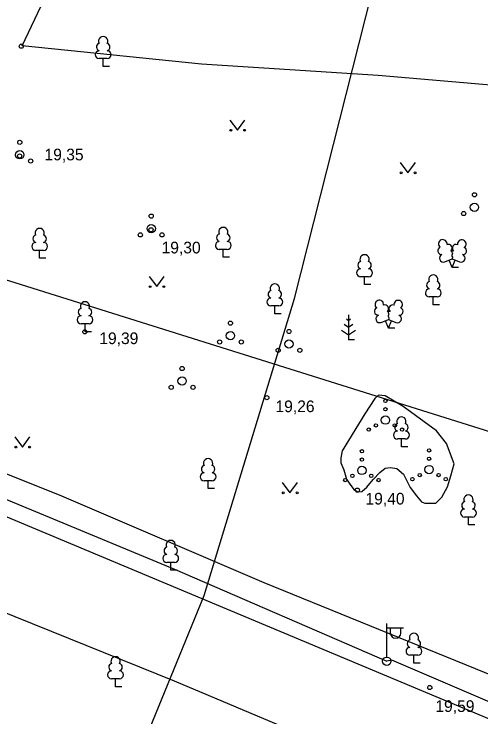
# Model space of a CAD drawing. Extents: x 713497 to 713863, y 6590062 to 6590327.
# Drawn here: x 713754.44 to 713782.43, y 6590236.16 to 6590278.31 of the extents above; entities that cross this region are included whole.
import ezdxf

# ---------------------------------------------------------------- set-up
doc = ezdxf.new("R2010")
doc.units = 0
for name, color, linetype in [('AED', 7, 'Continuous'), ('HALJASTUS', 7, 'Continuous'), ('KORGUS', 7, 'Continuous'), ('KPKAABEL', 7, 'Continuous'), ('MPKAABEL', 7, 'Continuous'), ('POST', 7, 'Continuous'), ('PUU', 7, 'Continuous'), ('SITRASS', 7, 'Continuous'), ('TEE', 7, 'Continuous'), ('TTRASS', 7, 'Continuous')]:
    doc.layers.add(name, color=color, linetype=linetype)

msp = doc.modelspace()

# ---------------------------------------------------------------- linework, layer by layer
at = {"layer": 'AED'}
msp.add_lwpolyline([(713788.88, 6590285.23), (713788.26, 6590278.65), (713788.03, 6590278.65), (713787.17, 6590278.25), (713785.85, 6590277.29), (713784.83, 6590276.5), (713784.01, 6590275.55), (713783.55, 6590274.76), (713783.25, 6590274.03), (713776.26, 6590274.62), (713765.67, 6590275.3), (713754.93, 6590276.41), (713757.56, 6590281.99), (713749.75, 6590289.16), (713748.93, 6590295.3), (713750.19, 6590299.43)], dxfattribs=at)
at = {"layer": 'HALJASTUS'}
for p, q in [((713767.367, 6590271.947), (713767.83, 6590271.34)), ((713767.83, 6590271.34), (713768.276, 6590271.947)), ((713777.587, 6590269.397), (713778.05, 6590268.79)), ((713778.05, 6590268.79), (713778.496, 6590269.397)), ((713762.527, 6590262.567), (713762.99, 6590261.96)), ((713762.99, 6590261.96), (713763.436, 6590262.567)), ((713754.477, 6590252.947), (713754.94, 6590252.34)), ((713754.94, 6590252.34), (713755.386, 6590252.947)), ((713770.517, 6590250.207), (713770.98, 6590249.6)), ((713770.98, 6590249.6), (713771.426, 6590250.207))]:
    msp.add_line(p, q, dxfattribs=at)
msp.add_lwpolyline([(713774.21, 6590250.97), (713774.36, 6590250.42), (713774.53, 6590250.17), (713774.8, 6590249.79), (713775.05, 6590249.66), (713775.28, 6590249.67), (713775.58, 6590249.94), (713775.96, 6590250.39), (713776.36, 6590250.81), (713776.69, 6590251.07), (713777.01, 6590251.11), (713777.39, 6590251.06), (713777.79, 6590250.71), (713778.19, 6590249.91), (713778.57, 6590249.41), (713778.87, 6590249.06), (713779.07, 6590248.97), (713779.44, 6590248.97), (713779.72, 6590248.97), (713780.09, 6590249.34), (713780.42, 6590249.96), (713780.62, 6590250.62), (713780.82, 6590251.34), (713780.37, 6590252.55), (713779.77, 6590253.32), (713777.77, 6590254.77), (713776.68, 6590255.42), (713776.29, 6590255.45), (713776.06, 6590255.25), (713775.46, 6590254.33), (713774.11, 6590252.12), (713774.03, 6590251.69), (713774.03, 6590251.39), (713774.21, 6590250.97)], dxfattribs=at)
for centre, radius in [((713767.429, 6590271.34), 0.055), ((713768.258, 6590271.34), 0.055), ((713754.78, 6590270.62), 0.125), ((713754.78, 6590269.87), 0.25), ((713755.43, 6590269.495), 0.125), ((713777.649, 6590268.79), 0.055), ((713778.478, 6590268.79), 0.055), ((713782.04, 6590267.47), 0.125), ((713782.04, 6590266.72), 0.25), ((713762.66, 6590266.19), 0.125), ((713781.39, 6590266.345), 0.125), ((713762.66, 6590265.44), 0.25), ((713762.01, 6590265.065), 0.125), ((713763.31, 6590265.065), 0.125), ((713762.589, 6590261.96), 0.055), ((713763.418, 6590261.96), 0.055), ((713767.41, 6590259.77), 0.125), ((713770.92, 6590259.27), 0.125), ((713767.41, 6590259.02), 0.25), ((713766.76, 6590258.645), 0.125), ((713768.06, 6590258.645), 0.125), ((713770.92, 6590258.52), 0.25), ((713770.27, 6590258.145), 0.125), ((713771.57, 6590258.145), 0.125), ((713764.51, 6590257.05), 0.125), ((713764.51, 6590256.3), 0.25), ((713763.86, 6590255.925), 0.125), ((713765.16, 6590255.925), 0.125), ((713776.7, 6590255.11), 0.1), ((713776.7, 6590254.61), 0.1), ((713776.7, 6590253.96), 0.25), ((713775.7, 6590253.385), 0.1), ((713776.135, 6590253.635), 0.1), ((713777.265, 6590253.635), 0.1), ((713777.7, 6590253.385), 0.1), ((713754.539, 6590252.34), 0.055), ((713755.368, 6590252.34), 0.055), ((713779.32, 6590252.14), 0.1), ((713775.29, 6590252.09), 0.1), ((713775.29, 6590251.59), 0.1), ((713779.32, 6590251.64), 0.1), ((713775.29, 6590250.94), 0.25), ((713779.32, 6590250.99), 0.25), ((713774.725, 6590250.615), 0.1), ((713775.855, 6590250.615), 0.1), ((713778.32, 6590250.415), 0.1), ((713778.755, 6590250.665), 0.1), ((713779.885, 6590250.665), 0.1), ((713780.32, 6590250.415), 0.1), ((713774.29, 6590250.365), 0.1), ((713776.29, 6590250.365), 0.1), ((713770.579, 6590249.6), 0.055), ((713771.408, 6590249.6), 0.055)]:
    msp.add_circle(centre, radius, dxfattribs=at)
at = {"layer": 'KORGUS'}
for centre in [(713754.87, 6590276.38), (713754.77, 6590269.8), (713762.65, 6590265.37), (713758.68, 6590259.25), (713769.59, 6590255.3), (713775.02, 6590249.76), (713779.36, 6590237.92)]:
    msp.add_circle(centre, 0.125, dxfattribs=at)
at = {"layer": 'KPKAABEL'}
msp.add_lwpolyline([(713815.88, 6590242.79), (713794.35, 6590249.68), (713754.19, 6590262.29), (713731.48, 6590269.02), (713706.45, 6590275.72)], dxfattribs=at)
at = {"layer": 'MPKAABEL'}
for points in [[(713701.219, 6590274.33), (713701.679, 6590274.524), (713703.015, 6590271.361), (713705.012, 6590272.169), (713706.295, 6590269.173), (713709.564, 6590267.835), (713721.885, 6590262.655), (713734.411, 6590257.594), (713748.424, 6590251.492), (713764.059, 6590245.013), (713776.78, 6590239.5)], [(713802.35, 6590228.73), (713777.08, 6590239.56), (713776.78, 6590239.5)]]:
    msp.add_lwpolyline(points, dxfattribs=at)
at = {"layer": 'POST'}
for p, q in [((713776.78, 6590239.75), (713776.78, 6590241.75)), ((713776.78, 6590241.5), (713777.78, 6590241.5)), ((713777.007, 6590241.179), (713777.007, 6590241.5)), ((713777.619, 6590241.179), (713777.619, 6590241.5))]:
    msp.add_line(p, q, dxfattribs=at)
msp.add_circle((713776.78, 6590239.5), 0.25, dxfattribs=at)
msp.add_arc((713777.313, 6590241.179), 0.306, 180, 0, dxfattribs=at)
at = {"layer": 'PUU'}
for p, q in [((713760.02, 6590275.635), (713759.54, 6590275.635)), ((713759.78, 6590275.16), (713759.78, 6590275.635)), ((713760.16, 6590275.16), (713759.78, 6590275.16)), ((713756.21, 6590264.135), (713755.73, 6590264.135)), ((713755.97, 6590263.66), (713755.97, 6590264.135)), ((713767.22, 6590264.195), (713766.74, 6590264.195)), ((713766.98, 6590263.72), (713766.98, 6590264.195)), ((713756.35, 6590263.66), (713755.97, 6590263.66)), ((713767.36, 6590263.72), (713766.98, 6590263.72)), ((713780.26, 6590263.445), (713780.705, 6590263.62)), ((713780.705, 6590263.62), (713781.145, 6590263.44)), ((713780.7, 6590263.11), (713780.525, 6590263.55)), ((713780.7, 6590263.11), (713780.88, 6590263.55)), ((713781.08, 6590263.11), (713780.7, 6590263.11)), ((713775.69, 6590262.555), (713775.21, 6590262.555)), ((713775.45, 6590262.08), (713775.45, 6590262.555)), ((713775.83, 6590262.08), (713775.45, 6590262.08)), ((713779.81, 6590261.345), (713779.33, 6590261.345)), ((713779.57, 6590260.87), (713779.57, 6590261.345)), ((713770.31, 6590260.805), (713769.83, 6590260.805)), ((713770.07, 6590260.33), (713770.07, 6590260.805)), ((713779.95, 6590260.87), (713779.57, 6590260.87)), ((713770.45, 6590260.33), (713770.07, 6590260.33)), ((713774.49, 6590260.27), (713774.49, 6590258.77)), ((713774.49, 6590259.92), (713774.366, 6590260.003)), ((713774.614, 6590260.003), (713774.49, 6590259.92)), ((713776.45, 6590259.815), (713776.895, 6590259.99)), ((713776.89, 6590259.48), (713776.715, 6590259.92)), ((713776.89, 6590259.48), (713777.07, 6590259.92)), ((713776.895, 6590259.99), (713777.335, 6590259.81)), ((713758.93, 6590259.735), (713758.45, 6590259.735)), ((713758.69, 6590259.26), (713758.69, 6590259.735)), ((713774.066, 6590259.359), (713774.49, 6590259.077)), ((713774.49, 6590259.52), (713774.223, 6590259.698)), ((713774.757, 6590259.698), (713774.49, 6590259.52)), ((713774.49, 6590259.077), (713774.914, 6590259.359)), ((713777.27, 6590259.48), (713776.89, 6590259.48)), ((713759.07, 6590259.26), (713758.69, 6590259.26)), ((713774.85, 6590258.77), (713774.49, 6590258.77)), ((713777.9, 6590252.825), (713777.42, 6590252.825)), ((713777.66, 6590252.35), (713777.66, 6590252.825)), ((713778.04, 6590252.35), (713777.66, 6590252.35)), ((713766.31, 6590250.325), (713765.83, 6590250.325)), ((713766.07, 6590249.85), (713766.07, 6590250.325)), ((713766.45, 6590249.85), (713766.07, 6590249.85)), ((713781.92, 6590248.145), (713781.44, 6590248.145)), ((713781.68, 6590247.67), (713781.68, 6590248.145)), ((713782.06, 6590247.67), (713781.68, 6590247.67)), ((713764.07, 6590245.425), (713763.59, 6590245.425)), ((713763.83, 6590244.95), (713763.83, 6590245.425)), ((713764.21, 6590244.95), (713763.83, 6590244.95)), ((713778.65, 6590239.855), (713778.17, 6590239.855)), ((713778.41, 6590239.38), (713778.41, 6590239.855)), ((713778.79, 6590239.38), (713778.41, 6590239.38)), ((713760.76, 6590238.445), (713760.28, 6590238.445)), ((713760.52, 6590237.97), (713760.52, 6590238.445)), ((713760.9, 6590237.97), (713760.52, 6590237.97))]:
    msp.add_line(p, q, dxfattribs=at)
for points in [[(713780.705, 6590264.115), (713780.685, 6590264.04), (713780.685, 6590264.02), (713780.695, 6590263.99), (713780.715, 6590263.955), (713780.72, 6590263.935), (713780.705, 6590263.9), (713780.68, 6590263.85), (713780.675, 6590263.825), (713780.68, 6590263.81), (713780.69, 6590263.78), (713780.725, 6590263.72), (713780.73, 6590263.7), (713780.725, 6590263.68), (713780.71, 6590263.645), (713780.705, 6590263.62)], [(713776.895, 6590260.485), (713776.875, 6590260.41), (713776.875, 6590260.39), (713776.885, 6590260.36), (713776.905, 6590260.325), (713776.91, 6590260.305), (713776.895, 6590260.27), (713776.87, 6590260.22), (713776.865, 6590260.195), (713776.87, 6590260.18), (713776.88, 6590260.15), (713776.915, 6590260.09), (713776.92, 6590260.07), (713776.915, 6590260.05), (713776.9, 6590260.015), (713776.895, 6590259.99)]]:
    msp.add_lwpolyline(points, dxfattribs=at)
for centre, radius, start, end in [((713759.78, 6590276.68), 0.277, 332.5799, 207.4201), ((713759.61, 6590276.333), 0.233, 109.0217, 253.1415), ((713759.95, 6590276.333), 0.233, 286.8508, 70.9859), ((713759.543, 6590275.872), 0.238, 90.0016, 269.3953), ((713760.017, 6590275.872), 0.238, 270.6047, 89.9984), ((713755.97, 6590265.18), 0.277, 332.5799, 207.4201), ((713766.98, 6590265.24), 0.277, 332.5799, 207.4201), ((713755.8, 6590264.833), 0.233, 109.0217, 253.1415), ((713756.14, 6590264.833), 0.233, 286.8508, 70.9859), ((713766.81, 6590264.893), 0.233, 109.0217, 253.1415), ((713767.15, 6590264.893), 0.233, 286.8508, 70.9859), ((713755.733, 6590264.372), 0.238, 90.0016, 269.3953), ((713756.207, 6590264.372), 0.238, 270.6047, 89.9984), ((713766.743, 6590264.432), 0.238, 90.0016, 269.3953), ((713767.217, 6590264.432), 0.238, 270.6047, 89.9984), ((713780.143, 6590264.524), 0.256, 111.5027, 232.5173), ((713780.143, 6590264.524), 0.256, 350.4856, 111.5002), ((713780.478, 6590264.274), 0.224, 308.5041, 111.5725), ((713780.941, 6590264.269), 0.225, 67.7016, 230.5126), ((713781.279, 6590264.515), 0.256, 67.6168, 188.6314), ((713781.279, 6590264.515), 0.256, 306.5997, 67.6143), ((713780.069, 6590264.113), 0.224, 111.4304, 274.4987), ((713780.704, 6590263.877), 0.237, 66.7655, 111.5015), ((713781.346, 6590264.103), 0.224, 264.6183, 67.6866), ((713775.45, 6590263.6), 0.277, 332.5799, 207.4201), ((713780.174, 6590263.668), 0.237, 111.5014, 291.5004), ((713781.235, 6590263.66), 0.237, 247.6166, 67.6155), ((713775.28, 6590263.253), 0.233, 109.0217, 253.1415), ((713775.62, 6590263.253), 0.233, 286.8508, 70.9859), ((713775.213, 6590262.792), 0.238, 90.0016, 269.3953), ((713775.687, 6590262.792), 0.238, 270.6047, 89.9984), ((713779.57, 6590262.39), 0.277, 332.5799, 207.4201), ((713770.07, 6590261.85), 0.277, 332.5799, 207.4201), ((713779.4, 6590262.043), 0.233, 109.0217, 253.1415), ((713779.74, 6590262.043), 0.233, 286.8508, 70.9859), ((713769.9, 6590261.503), 0.233, 109.0217, 253.1415), ((713770.24, 6590261.503), 0.233, 286.8508, 70.9859), ((713779.333, 6590261.582), 0.238, 90.0016, 269.3953), ((713779.807, 6590261.582), 0.238, 270.6047, 89.9984), ((713758.69, 6590260.78), 0.277, 332.5799, 207.4201), ((713769.833, 6590261.042), 0.238, 90.0016, 269.3953), ((713770.307, 6590261.042), 0.238, 270.6047, 89.9984), ((713776.333, 6590260.894), 0.256, 111.5027, 232.5173), ((713776.333, 6590260.894), 0.256, 350.4856, 111.5002), ((713777.469, 6590260.885), 0.256, 67.6168, 188.6314), ((713777.469, 6590260.885), 0.256, 306.5997, 67.6143), ((713758.52, 6590260.433), 0.233, 109.0217, 253.1415), ((713758.86, 6590260.433), 0.233, 286.8508, 70.9859), ((713776.259, 6590260.483), 0.224, 111.4304, 274.4987), ((713776.668, 6590260.644), 0.224, 308.5041, 111.5725), ((713777.131, 6590260.639), 0.225, 67.7016, 230.5126), ((713777.536, 6590260.473), 0.224, 264.6183, 67.6866), ((713758.453, 6590259.972), 0.238, 90.0016, 269.3953), ((713758.927, 6590259.972), 0.238, 270.6047, 89.9984), ((713776.364, 6590260.038), 0.237, 111.5014, 291.5004), ((713776.894, 6590260.247), 0.237, 66.7655, 111.5015), ((713777.425, 6590260.03), 0.237, 247.6166, 67.6155), ((713777.66, 6590253.87), 0.277, 332.5799, 207.4201), ((713777.49, 6590253.523), 0.233, 109.0217, 253.1415), ((713777.83, 6590253.523), 0.233, 286.8508, 70.9859), ((713777.423, 6590253.062), 0.238, 90.0016, 269.3953), ((713777.897, 6590253.062), 0.238, 270.6047, 89.9984), ((713766.07, 6590251.37), 0.277, 332.5799, 207.4201), ((713765.9, 6590251.023), 0.233, 109.0217, 253.1415), ((713766.24, 6590251.023), 0.233, 286.8508, 70.9859), ((713765.833, 6590250.562), 0.238, 90.0016, 269.3953), ((713766.307, 6590250.562), 0.238, 270.6047, 89.9984), ((713781.68, 6590249.19), 0.277, 332.5799, 207.4201), ((713781.51, 6590248.843), 0.233, 109.0217, 253.1415), ((713781.85, 6590248.843), 0.233, 286.8508, 70.9859), ((713781.443, 6590248.382), 0.238, 90.0016, 269.3953), ((713781.917, 6590248.382), 0.238, 270.6047, 89.9984), ((713763.83, 6590246.47), 0.277, 332.5799, 207.4201), ((713763.66, 6590246.123), 0.233, 109.0217, 253.1415), ((713764, 6590246.123), 0.233, 286.8508, 70.9859), ((713763.593, 6590245.662), 0.238, 90.0016, 269.3953), ((713764.067, 6590245.662), 0.238, 270.6047, 89.9984), ((713778.41, 6590240.9), 0.277, 332.5799, 207.4201), ((713778.24, 6590240.553), 0.233, 109.0217, 253.1415), ((713778.58, 6590240.553), 0.233, 286.8508, 70.9859), ((713778.173, 6590240.092), 0.238, 90.0016, 269.3953), ((713778.647, 6590240.092), 0.238, 270.6047, 89.9984), ((713760.52, 6590239.49), 0.277, 332.5799, 207.4201), ((713760.35, 6590239.143), 0.233, 109.0217, 253.1415), ((713760.69, 6590239.143), 0.233, 286.8508, 70.9859), ((713760.283, 6590238.682), 0.238, 90.0016, 269.3953), ((713760.757, 6590238.682), 0.238, 270.6047, 89.9984)]:
    msp.add_arc(centre, radius, start, end, dxfattribs=at)
at = {"layer": 'SITRASS'}
msp.add_lwpolyline([(713863.358, 6590205.976), (713841.44, 6590214.83), (713823.81, 6590222.07), (713798.2, 6590232.48), (713769.43, 6590244.2), (713757.31, 6590249.39), (713740.65, 6590256.05), (713706.71, 6590269.85)], dxfattribs=at)
at = {"layer": 'TEE'}
for points in [[(713705.99, 6590269.548), (713709.56, 6590266.765), (713802.48, 6590227.84), (713863.358, 6590202.427)], [(713863.358, 6590196.431), (713764.059, 6590238.297), (713742.86, 6590246.85), (713734.952, 6590249.165), (713734.699, 6590248.565), (713734.18, 6590247.457), (713733.715, 6590246.43), (713733.203, 6590245.297), (713732.677, 6590244.133), (713734.573, 6590241.161), (713736.147, 6590238.694), (713748.431, 6590232.928), (713760.369, 6590227.324), (713754.579, 6590213.72), (713745.812, 6590217.88), (713744.782, 6590218.369), (713743.276, 6590218.882), (713741.882, 6590218.856), (713740.847, 6590218.526), (713739.892, 6590217.92), (713738.92, 6590215.76), (713731.142, 6590198.62)]]:
    msp.add_lwpolyline(points, dxfattribs=at)
at = {"layer": 'TTRASS'}
msp.add_lwpolyline([(713715.14, 6590205.42), (713715.96, 6590207.06), (713723.64, 6590202.93), (713744.47, 6590191.47), (713758.55, 6590225.65), (713765.83, 6590243.44), (713771.25, 6590261.26), (713780.18, 6590296.56)], dxfattribs=at)

# ---------------------------------------------------------------- texts
at = {"layer": 'KORGUS'}
for s, p in [('19,35', (713756.263, 6590269.535)), ('19,30', (713763.281, 6590263.955)), ('19,39', (713759.546, 6590258.515)), ('19,26', (713770.11, 6590254.435)), ('19,40', (713775.506, 6590248.895)), ('19,59', (713779.696, 6590236.455))]:
    msp.add_text(s, height=0.7, dxfattribs=at).set_placement(p)

doc.saveas('drawing.dxf')
